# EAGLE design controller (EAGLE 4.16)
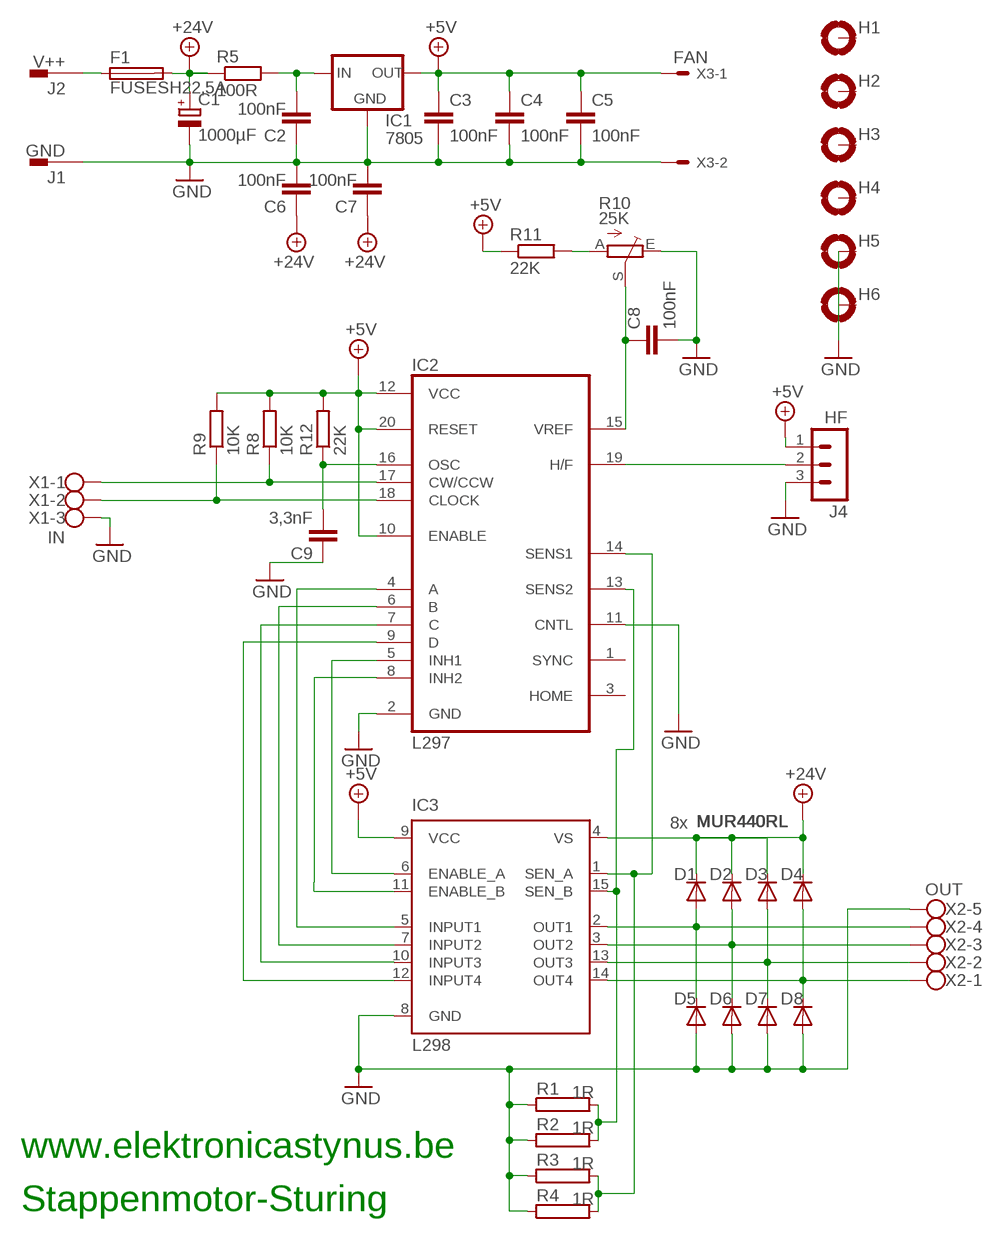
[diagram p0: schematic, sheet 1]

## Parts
C1  1000µF  CPOL-EUE7.5-16  [E7,5-16]
C2  100nF  C-EU050-025X075  [C050-025X075]
C3  100nF  C-EU050-025X075  [C050-025X075]
C4  100nF  C-EU050-025X075  [C050-025X075]
C5  100nF  C-EU050-025X075  [C050-025X075]
C6  100nF  C-EU050-025X075  [C050-025X075]
C7  100nF  C-EU050-025X075  [C050-025X075]
C8  100nF  C-EU050-030X075  [C050-030X075]
C9  3,3nF  C-EU050-025X075  [C050-025X075]
D1  MUR440RL  [C2673]
D2  MUR440RL  [C2673]
D3  MUR440RL  [C2673]
D4  MUR440RL  [C2673]
D5  MUR440RL  [C2673]
D6  MUR440RL  [C2673]
D7  MUR440RL  [C2673]
D8  MUR440RL  [C2673]
F1  FUSESH22,5A  [SH22,5A]
H1  MOUNT-PAD-ROUND3.0  [3,0-PAD]
H2  MOUNT-PAD-ROUND3.0  [3,0-PAD]
H3  MOUNT-PAD-ROUND3.0  [3,0-PAD]
H4  MOUNT-PAD-ROUND3.0  [3,0-PAD]
H5  MOUNT-PAD-ROUND3.0  [3,0-PAD]
H6  MOUNT-PAD-ROUND3.0  [3,0-PAD]
IC1  7805  78XXS  [78XXS]
IC2  L297  [DIL20]
IC3  L298  [MULTIWATT-15]
J1  GND  PIN2F061.220  [F061.220]
J2  V++  PIN2F061.220  [F061.220]
J4  HF  MA03-1  [MA03-1]
R1  1R  RKH206-8  [KH206-8]
R2  1R  RKH206-8  [KH206-8]
R3  1R  RKP292  [KP292]
R4  1R  RKP292  [KP292]
R5  100R  R-EU_0617/22  [0617/22]
R8  10K  R-EU_0204/7  [0204/7]
R9  10K  R-EU_0204/7  [0204/7]
R10  25K  TRIM_EU-CA9V  [CA9V]
R11  22K  R-EU_0204/7  [0204/7]
R12  22K  R-EU_0204/7  [0204/7]
X1  IN  W237-03P  [W237-133]
X2  OUT  W237-05P  [W237-5P]
X3  FAN  22-23-2021  [22-23-2021]

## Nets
+5V: C3.1 C4.1 C5.1 IC1.OUT IC2.10(ENABLE) IC2.12(VCC) IC2.20(RESET) IC3.9(VCC) J4.1 R8.2 R9.2 R11.1 R12.2 X3.1
+24V: C1.+ C6.1 C7.1 D1.C D2.C D3.C D4.C F1.2 IC3.4(VS) R5.1
GND: C1.- C2.1 C3.2 C4.2 C5.2 C6.2 C7.2 C8.2 C9.1 D5.A D6.A D7.A D8.A H5.B3,0(MOUNT) H6.B3,0(MOUNT) IC1.GND IC2.2(GND) IC2.11(CNTL) IC3.8(GND) J1.1A J4.3 R1.1 R2.1 R3.1 R4.1 R10.E X1.3 X2.5 X3.2
N$1: F1.1 J2.1A
N$2: C2.2 IC1.IN R5.2
N$4: IC2.13(SENS2) IC3.15(SEN_B) R1.2 R2.2
N$5: IC2.14(SENS1) IC3.1(SEN_A) R3.2 R4.2
N$7: IC2.6(B) IC3.7(INPUT2)
N$8: IC2.5(INH1) IC3.6(ENABLE_A)
N$9: IC2.8(INH2) IC3.11(ENABLE_B)
N$10: IC2.4(A) IC3.5(INPUT1)
N$11: IC2.7(C) IC3.10(INPUT3)
N$12: IC2.9(D) IC3.12(INPUT4)
N$13: IC2.19(H/F) J4.2
N$14: IC2.18(CLOCK) R9.1 X1.2
N$15: D1.A D5.C IC3.2(OUT1) X2.4
N$16: D2.A D6.C IC3.3(OUT2) X2.3
N$17: D4.A D8.C IC3.14(OUT4) X2.1
N$19: IC2.17(CW/CCW) R8.1 X1.1
N$20: C8.1 IC2.15(VREF) R10.S
N$21: R10.A R11.2
N$22: C9.2 IC2.16(OSC) R12.1
N$23: D3.A D7.C IC3.13(OUT3) X2.2
Unconnected: H1.B3,0(MOUNT) H2.B3,0(MOUNT) H3.B3,0(MOUNT) H4.B3,0(MOUNT) IC2.1(SYNC) IC2.3(HOME) J1.1B J2.1B

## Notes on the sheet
- 8x
- www.elektronicastynus.be
- Stappenmotor-Sturing

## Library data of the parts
C1 = rcl:CPOL-EU: POLARIZED CAPACITOR, European symbol
C2-C9 = rcl:C-EU: CAPACITOR, European symbol
D1-D8 = diode:MUR440RL: DIODE
F1 = fuse:FUSE: Fuse
H1-H6 = holes:MOUNT-PAD-ROUND: MOUNTING PAD, round
IC1 = v-reg:78XXS: VOLTAGE REGULATOR
IC2 = st-microelectronics:L297: STEPPER MOTOR CONTROLLER
IC3 = st-microelectronics:L298: DUAL FULL-BRIDGE DRIVER
J1 J2 = con-faston:PIN2: Flachstecker Typ tyco/Electronics/AMP
J4 = con-lstb:MA03-1: PIN HEADER
R1-R4 = resistor-power:R: Power Resitor
R5 R8 R9 R11 R12 = rcl:R-EU_: RESISTOR, European symbol
R10 = pot:TRIM_EU-: POTENTIOMETER
X1 = con-wago-508:W237-03P: WAGO SREW CLAMP
X2 = con-wago-508:W237-05P: WAGO SREW CLAMP
X3 = con-molex:22-23-2021: .100" (2.54mm) Center Header - 2 Pin

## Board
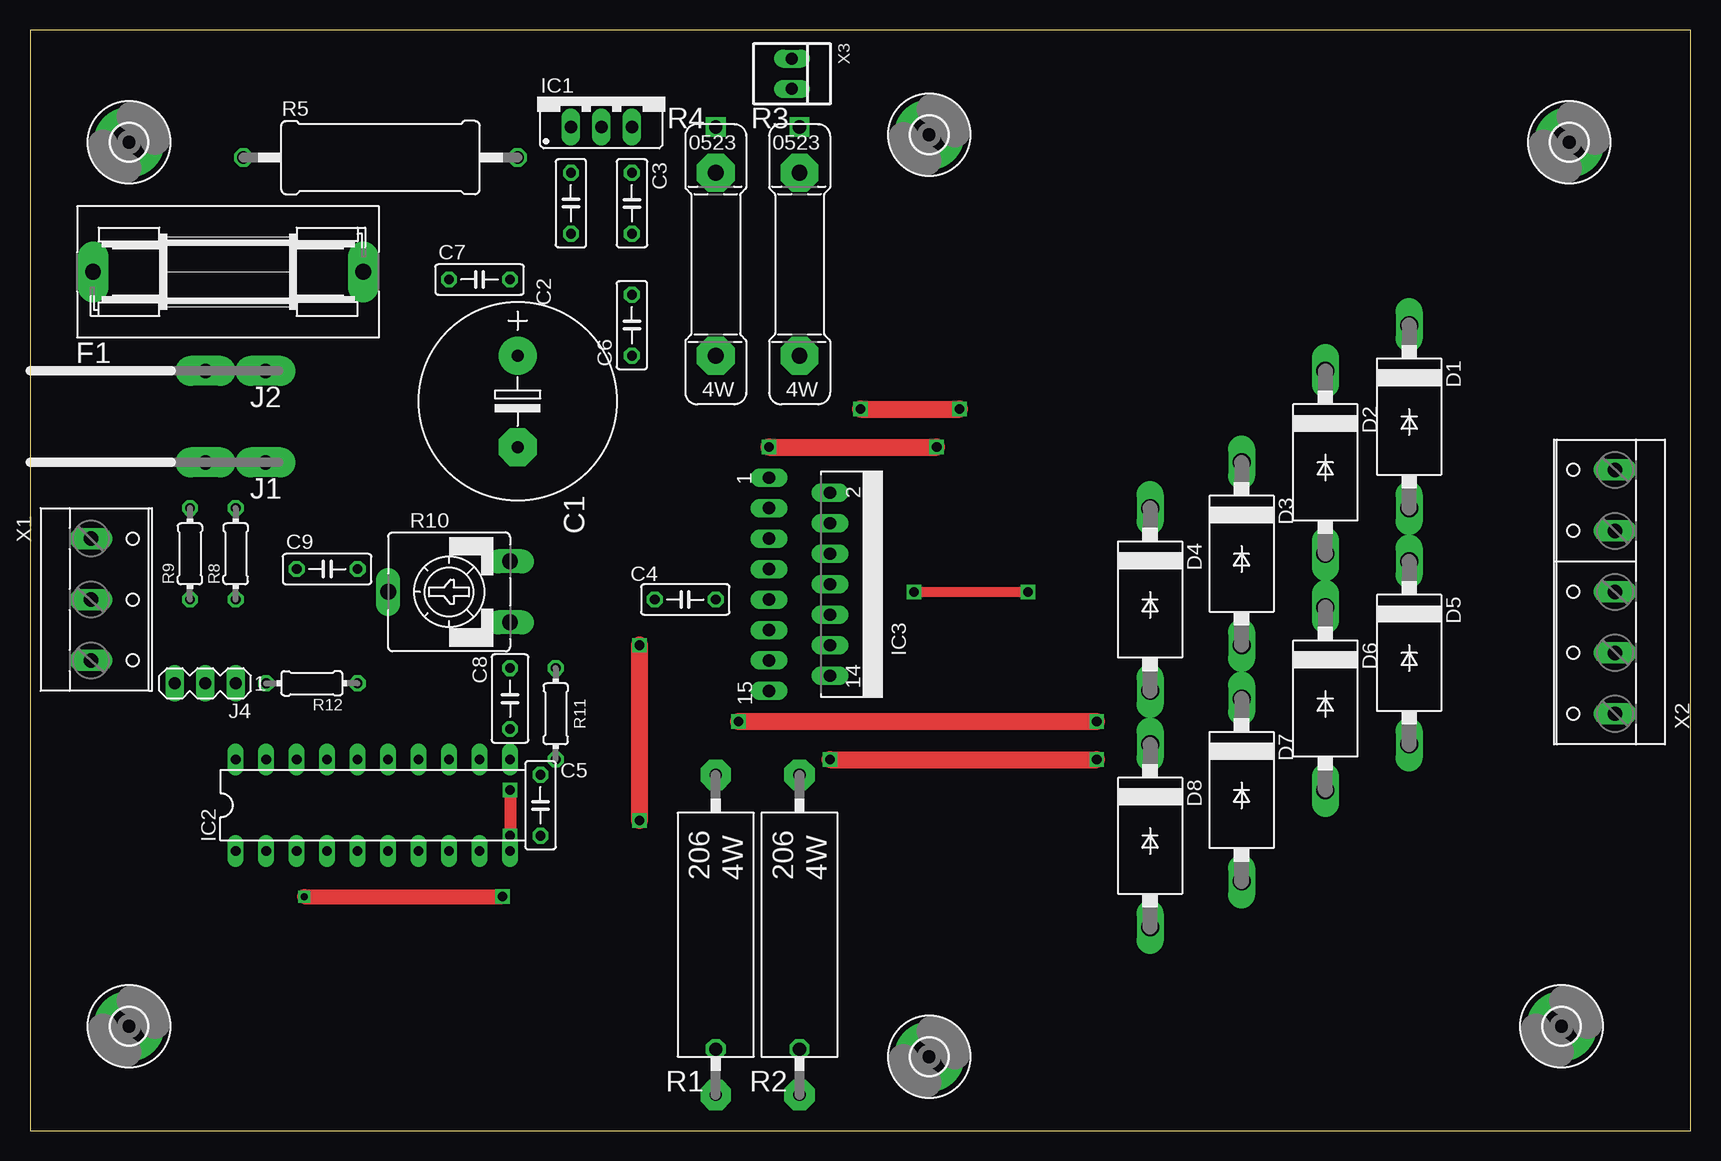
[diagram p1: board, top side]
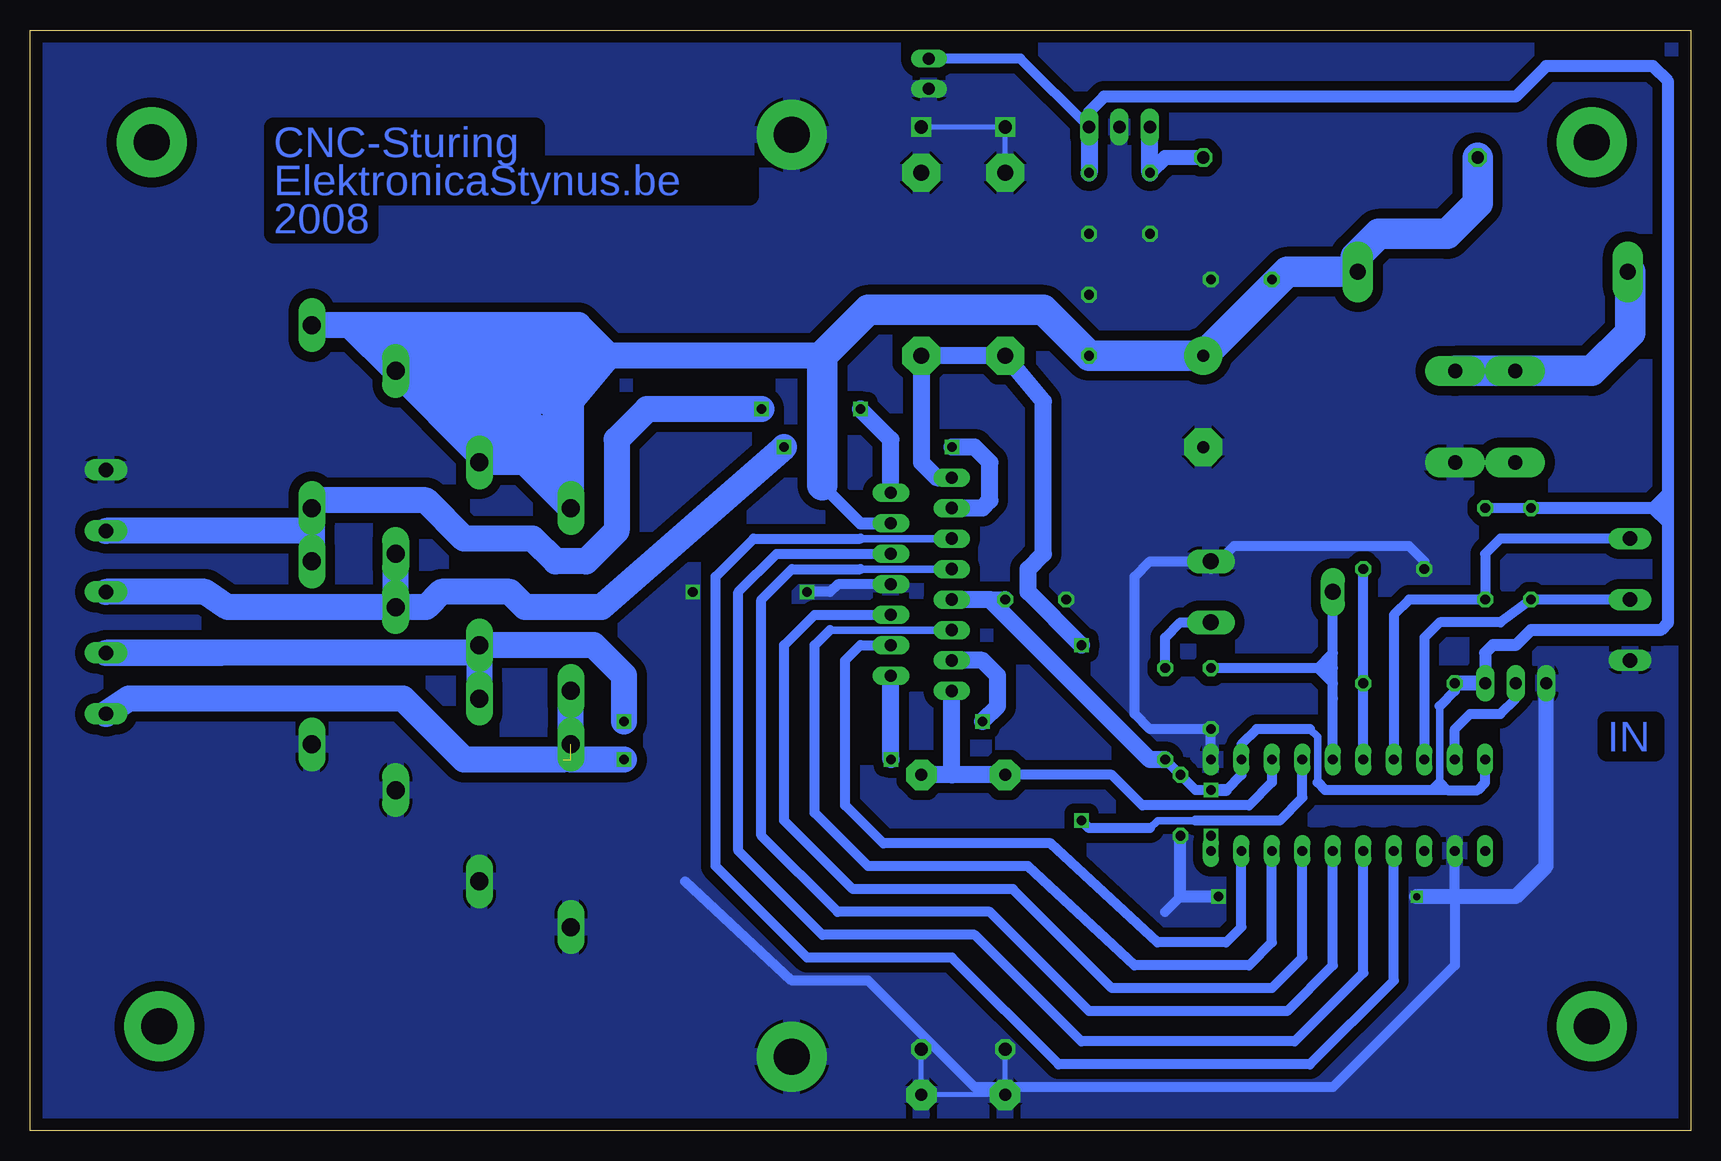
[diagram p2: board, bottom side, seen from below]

Size 138.41 x 91.75 mm. Coordinates in mm from the lower left corner, seen from the top.
Outline: 0,0 138.41,0 138.41,91.75 0,91.75 0,0
Copper layers (1*16): Top 0.035mm / dielectric 1.5mm / Bottom 0.035mm
Design rules "default": minimum track width 10mil, minimum drill 24mil, track to track 8mil, track to pad 8mil, pad to pad 8mil, via to via 8mil, smd to smd 8mil, copper to edge 40mil, drill to drill 8mil, minimum pad ring 10mil, minimum via ring 8mil, stop-mask expansion 4mil, vias tented up to drill 0mil, thermal gap 10mil

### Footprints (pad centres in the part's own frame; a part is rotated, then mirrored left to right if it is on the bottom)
E7,5-16 = drill 1.016 pad 3.15 round: + -3.81,0 | drill 1.016 pad 3.15 octagon: - 3.81,0
C050-025X075 = drill 0.813 octagon: 1 -2.54,0; 2 2.54,0
C050-030X075 = drill 0.813 octagon: 1 -2.54,0; 2 2.54,0
C2673 = drill 1.499 long: A 7.62,0; C -7.62,0
SH22,5A = drill 1.321 pad 2.54 long: 1 -11.252,0; 2 11.252,0
3,0-PAD = drill 3 pad 5.842 round: B3,0 0,0
78XXS = drill 1.016 long: GND 0,-2.54; IN -2.54,-2.54; OUT 2.54,-2.54
DIL20 = drill 0.813 long: 1 -11.43,-3.81; 2 -8.89,-3.81; 3 -6.35,-3.81; 4 -3.81,-3.81; 5 -1.27,-3.81; 6 1.27,-3.81; 7 3.81,-3.81; 8 6.35,-3.81; 9 8.89,-3.81; 10 11.43,-3.81; 11 11.43,3.81; 12 8.89,3.81; 13 6.35,3.81; 14 3.81,3.81; 15 1.27,3.81; 16 -1.27,3.81; 17 -3.81,3.81; 18 -6.35,3.81; 19 -8.89,3.81; 20 -11.43,3.81
MULTIWATT-15 = drill 1.016 long: 1 -8.89,-7.62; 2 -7.62,-2.54; 3 -6.35,-7.62; 4 -5.08,-2.54; 5 -3.81,-7.62; 6 -2.54,-2.54; 7 -1.27,-7.62; 8 0,-2.54; 9 1.27,-7.62; 10 2.54,-2.54; 11 3.81,-7.62; 12 5.08,-2.54; 13 6.35,-7.62; 14 7.62,-2.54; 15 8.89,-7.62
F061.220 = drill 1.2 pad 2.5 long: 1A -2.5,0; 1B 2.5,0
MA03-1 = drill 1.016 long: 1 -2.54,0; 2 0,0; 3 2.54,0
KH206-8 = drill 1.016 pad 2.54 octagon: 1 -13.335,0; 2 13.335,0
KP292 = drill 1.321 pad 3.15 octagon: 1 -7.62,0; 2 7.62,0
0617/22 = drill 1.016 octagon: 1 -11.43,0; 2 11.43,0
0204/7 = drill 0.813 octagon: 1 -3.81,0; 2 3.81,0
CA9V = drill 1.321 long: A -2.54,-5.08; E 2.54,-5.08; S 0,5.08
W237-133 = drill 1.194 long: 1 -5.08,-0.635; 2 0,-0.635; 3 5.08,-0.635
W237-5P = drill 1.194 long: 1 -10.16,-0.635; 2 -5.08,-0.635; 3 0,-0.635; 4 5.08,-0.635; 5 10.16,-0.635
22-23-2021 = drill 1 long: 1 -1.27,0; 2 1.27,0

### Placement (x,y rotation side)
C1  40.63,60.79 270 top
C2  45.08,77.31 90 top
C3  50.16,77.31 270 top
C4  54.61,44.28 180 top
C5  42.54,27.14 270 top
C6  50.16,67.15 90 top
C7  37.46,70.96 0 top
C8  40,36.03 270 top
C9  24.76,46.82 0 top
D1  114.93,59.52 270 top
D2  107.94,55.71 270 top
D3  100.96,48.09 270 top
D4  93.34,44.28 270 top
D5  114.93,39.84 270 top
D6  107.94,36.03 270 top
D7  100.96,28.41 270 top
D8  93.34,24.6 270 top
F1  16.51,71.59 0 top
H1  8.25,8.72 0 top
H2  127.63,8.72 0 top
H3  8.25,82.39 0 top
H4  128.26,82.39 0 top
H5  74.92,6.19 0 top
H6  74.92,83.02 0 top
IC1  47.62,86.2 0 top
IC2  28.57,27.14 0 top
IC3  69.21,45.55 270 top
J1  17.14,55.71 180 top
J2  17.14,63.34 180 top
J4  14.6,37.3 180 top
R1  57.14,16.34 90 top
R2  64.13,16.34 90 top
R3  64.13,72.23 270 top
R4  57.14,72.23 270 top
R5  29.2,81.12 0 top
R8  17.14,48.09 90 top
R9  13.33,48.09 90 top
R10  34.92,44.92 90 top
R11  43.81,34.76 90 top
R12  23.49,37.3 180 top
X1  5.71,44.28 270 top
X2  131.44,44.92 90 top
X3  63.5,88.1 270 top

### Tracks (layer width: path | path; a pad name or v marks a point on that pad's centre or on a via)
+5V  (via drill 0.8)
  Top 1.016: v40,28.41 v40,24.6
  Bottom 0.61: 20.95,35.39 20.95,29.05 | 31.11,29.05 31.11,32.85 31.74,33.49
  Bottom 0.813: v40,28.41 41.27,28.41 C5.1 R11.1 | 38.73,28.41 37.46,29.68 IC2.12 37.46,32.22 36.19,33.49 31.74,33.49 | R12.2 19.68,36.66 20.95,35.39 | 20.31,28.41 17.77,28.41 17.14,29.05 IC2.20 | 20.31,28.41 20.95,29.05 21.59,28.41 20.31,28.41 | 20.31,28.41 30.48,28.41 31.11,29.05 | R9.2 R8.2 | X3.1 55.88,89.37 IC1.OUT
  Bottom 1.016: J4.1 17.14,39.84 16.51,40.48 14.6,40.48 13.33,41.74 2.54,41.74 1.9,42.38 1.9,50.63 | 1.9,50.63 3.17,51.91 | 3.17,51.91 R9.2 | C3.1 IC1.OUT 50.16,84.93 48.89,86.2 14.6,86.2 12.06,88.73 3.17,88.73 1.9,87.47 1.9,52.54 | 3.17,51.91 1.9,53.17 1.9,52.54 | 1.9,50.63 1.9,52.54 | 1.9,52.54 2.54,51.91 | v40,24.6 IC2.10 | 38.73,28.41 v40,28.41
  Bottom 1.27: J4.1 R12.2
  Bottom 1.422: IC1.OUT C3.1 | 58.41,44.28 IC3.9 | R11.1 45.08,30.95 58.41,44.28 | 58.41,44.28 C4.1
+24V
  Bottom 0.813: C7.1 34.28,70.96 33.65,71.59 | C1.+ C6.1
  Bottom 1.016: 72.39,53.81 69.21,50.63 IC3.4
  Bottom 2.184: D2.C 107.94,65.88 109.22,67.15 111.75,67.15 | D2.C 107.94,62.7 106.67,62.7 | 100.96,56.35 D3.C 97.15,55.71 D4.C | 100.96,56.35 100.96,60.79 102.86,62.7 106.67,62.7 | 90.16,64.61 93.34,60.79 D4.C | 72.39,64.61 90.16,64.61 | 108.58,67.15 92.7,67.15 90.16,64.61 | 108.58,67.15 111.75,67.15 | 111.75,67.15 D1.C | 108.58,67.15 D4.C | D2.C 100.96,56.35 | 111.75,67.15 D2.C | 95.25,57.62 97.15,59.52 97.15,57.62 100.96,57.62 102.23,58.89 102.86,58.89 106.67,62.7
  Bottom 2.54: 72.39,53.81 72.39,64.61 68.58,68.42 53.97,68.42 C6.1 C1.+ 33.65,71.59 27.94,71.59 | R5.1 17.77,77.31 20.31,74.77 26.03,74.77 27.94,72.86 27.94,71.59 | 27.94,71.59 F1.2
GND  (via drill 0.6, 0.8, 1.1)
  Top 0.813: v73.66,44.92 v83.18,44.92
  Top 1.016: v22.85,19.52 v39.37,19.52
  Top 1.27: v22.85,19.52 v39.37,19.52
  Bottom 0.406: v57.14,6.82 R1.1 R2.1 v64.13,6.82 | R4.1 v57.14,83.66 v64.13,83.66
  Bottom 0.813: IC2.11 C8.2 45.08,33.49 46.35,34.76 46.35,46.19 45.08,47.46 R10.E | 22.22,47.46 23.49,48.73 38.09,48.73 40,46.82 | IC2.2 19.68,19.52 19.68,13.81 29.84,3.65 59.69,3.65 68.58,12.54 74.92,12.54 83.81,20.79 | v73.66,44.92 71.75,44.92 71.11,45.55 IC3.8 | 42.54,19.52 43.81,18.25
  Bottom 1.016: C5.2 42.54,19.52 v39.37,19.52 | v22.85,19.52 19.68,19.52
  Bottom 1.27: 64.77,3.01 64.13,2.37 | J4.3 12.06,22.06 14.6,19.52 v22.85,19.52
  pour Bottom (isolate 0.813): 0.63,90.64 137.16,90.64 137.16,0.47 0.63,0.47
N$1
  Bottom 2.54: J2.1A 8.25,63.34 5.08,66.51 5.08,71.59 F1.1
N$2
  Bottom 1.27: R5.2 43.81,81.12 C2.2
  Bottom 1.422: C2.2 IC1.IN
N$3
  Bottom 2.184: 91.44,64.61 92.7,64.61 93.34,65.24 107.31,65.24 107.31,63.97 93.34,63.97 92.7,63.34 100.33,63.34 100.96,62.7 95.25,62.7 93.97,61.43 100.33,61.43 100.33,57.62 99.69,56.98 96.52,56.98 94.61,55.08 94.61,60.16 95.25,60.79 96.52,60.79 99.05,58.25 99.05,60.16
N$4
  Bottom 0.813: IC2.13 34.92,29.05 36.82,27.14 45.71,27.14 48.25,29.68 R1.2
  Bottom 1.422: 61.59,29.68 IC3.15 | 61.59,29.68 R2.2 | R1.2 61.59,29.68
N$5  (via drill 0.8)
  Top 1.422: v50.8,25.87 v50.8,40.48
  Bottom 0.61: 41.27,25.87 44.45,25.87 45.08,25.23
  Bottom 0.813: IC2.14 32.38,27.77 34.28,25.87 41.27,25.87 | 45.08,25.23 50.16,25.23 v50.8,25.87
  Bottom 1.422: v50.8,40.48 55.24,44.92 55.24,46.82 53.97,48.09 53.97,60.79 R4.2 R3.2 64.13,55.71 62.86,54.45 IC3.1
N$7
  Bottom 0.61: 69.21,46.82 IC3.7
  Bottom 0.813: IC2.6 29.84,13.81 33.65,10 50.16,10 58.41,18.25 71.11,18.25 77.47,24.6 77.47,44.28 74.92,46.82 69.21,46.82
N$8
  Bottom 0.813: IC2.5 27.3,13.17 33.02,7.46 50.8,7.46 59.69,16.34 72.39,16.34 79.37,23.33 79.37,44.92 76.19,48.09 IC3.6
N$9
  Bottom 0.61: 71.75,41.74 IC3.11
  Bottom 0.813: IC2.8 34.92,15.71 36.82,13.81 46.35,13.81 55.24,22.06 68.58,22.06 73.02,26.5 73.02,40.48 71.75,41.74
N$10
  Bottom 0.61: 69.21,49.37 IC3.5
  Bottom 0.813: IC2.4 24.76,12.54 31.74,5.55 52.7,5.55 61.59,14.44 73.66,14.44 81.28,22.06 81.28,46.19 78.1,49.37 69.21,49.37
N$11
  Bottom 0.813: IC2.7 32.38,14.44 34.92,11.9 48.25,11.9 56.51,20.15 69.84,20.15 75.56,25.87 75.56,40.48 73.02,43.02 IC3.10
N$12
  Bottom 0.813: IC3.12 69.21,40.48 70.48,39.2 70.48,27.14 67.3,23.96 53.34,23.96 44.45,15.71 38.73,15.71 37.46,16.98 IC2.9
N$13
  Bottom 0.813: J4.2 14.6,36.03 15.87,34.76 18.41,34.76 19.68,33.49 IC2.19
N$14
  Bottom 0.813: X1.2 R9.1 15.87,42.38 20.95,42.38 22.22,41.11 IC2.18
N$15  (via drill 0.8)
  Top 1.422: v69.21,60.16 v77.47,60.16
  Bottom 1.422: v69.21,60.16 66.67,57.62 IC3.2
  Bottom 2.184: v77.47,60.16 86.99,60.16 89.53,57.62 89.53,50 92.07,47.46 94.61,47.46 96.52,49.37 102.23,49.37 105.41,52.54 114.3,52.54 D1.A 114.93,50 | 114.93,50 D5.C | 114.93,50 X2.4
N$16  (via drill 0.8)
  Top 1.422: v61.59,56.98 v75.56,56.98
  Bottom 1.422: IC3.3 59.05,51.91 58.41,52.54 58.41,55.71 59.69,56.98 v61.59,56.98
  Bottom 2.184: v75.56,56.98 90.8,43.65 97.15,43.65 98.42,44.92 104.14,44.92 105.41,43.65 D6.C | D6.C 121.91,43.65 123.82,44.92 X2.3 | D6.C D2.A
N$17  (via drill 0.8)  (2 unrouted)
  Top 1.422: v66.67,30.95 v88.89,30.95
  Bottom 1.422: v66.67,30.95 IC3.14
  Bottom 2.184: 93.97,30.95 102.23,30.95 107.31,36.03 130.17,36.03 X2.1 | D8.C D4.A | v88.89,30.95 93.34,30.95
N$19
  Bottom 0.813: X1.1 15.87,49.37 17.14,48.09 R8.1 23.49,44.28 24.76,43.02 IC2.17
N$20
  Bottom 0.813: 31.11,38.57 C8.1 | IC2.15 29.84,36.03 | 29.84,39.84 R10.S | 31.11,38.57 29.84,39.84 | 29.84,38.57 29.84,39.84 | 29.84,36.03 29.84,38.57 | 29.84,36.03 29.84,37.3 31.11,38.57 | 29.84,38.57 31.11,38.57
N$21
  Bottom 0.813: R10.A 42.54,42.38 43.81,41.11 R11.2
N$22
  Bottom 0.813: IC2.16 R12.1 C9.2
N$23  (via drill 0.8)
  Top 1.422: v59.05,34.12 v88.89,34.12
  Bottom 1.422: IC3.13 59.05,39.2 57.78,37.93 57.78,35.39 v59.05,34.12
  Bottom 2.184: v88.89,34.12 88.89,37.93 91.44,40.48 D3.A 100.96,39.84 | 100.96,37.3 D7.C 100.96,39.84 | 100.96,39.84 X2.2 122.55,39.84

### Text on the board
Bottom: CNC-Sturing | ElektronicaStynus.be | 2008 | IN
